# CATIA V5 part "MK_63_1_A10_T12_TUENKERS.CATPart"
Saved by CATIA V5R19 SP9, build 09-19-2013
Part number: MK_63_1_A10_T12_TUENKERS
Material "MISCHDICHTE": density 5230.5 kg/m3, Young's modulus 2e+11 Pa, Poisson ratio 0.266
Bounding box of the stored display mesh (mm): x -193.5 to 132.266, y -121.5 to 144, z -40 to 122.161
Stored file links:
  G:\Konstruktion\Modelle\Catia_V5\MK_63_1_A10_T12_TUENKERS.CATPart
  G:\Konstruktion\Modelle\Catia_V5\Spannarme\SPANNARM_KPL_63_A10_217498_TUENKERS.CATPart
  C:\Catia\Tuenkers_B19SP9HF86_64\win_b64\reffiles\standard\MetricThickPitch.txt
  G:\Konstruktion\Modelle\Catia_V5\MK_63_1_A10_T00_TUENKERS.CATPart
  G:\Konstruktion\Modelle\Catia_V5\MK2_63_1_A40_T12_TUENKERS.CATPart
  HANDHEBEL_KPL_50_63_TUENKERS.CATPart
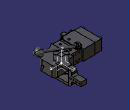
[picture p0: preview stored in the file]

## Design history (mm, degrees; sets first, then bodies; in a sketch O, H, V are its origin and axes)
AxisSystem1: origin (0, 0, 0), X (1, 0, 0), Y (0, 1, 0), Z (0, 0, 1)
Body1 (main body)
  Body2 "*DIT1\\*DIT2\\"
    Solid1: solid without history
  Assemble1: tool Body2
  Body3 "*DIT1\\*DIT3"
    Solid2 "Solid.1": solid without history
  Assemble2: tool Body3
  Body4 "*DIT1\\*DIT12\\*DIT16\\"
    Solid3 "Solid.1": solid without history
  Assemble3: tool Body4
  Body5 "*DIT1\\*DIT12\\*DIT17\\"
    Solid4 "Solid.1": solid without history
  Assemble4: tool Body5
  Body6 "*DIT1\\*DIT12\\MK_MK2_63_1_A10_A11_A12_T12_081112_3D_xSET4_2.1"
    Solid5 "Solid.1": solid without history
    Body7 "*DIT1\\*DIT12\\MK_MK2_63_1_A10_A11_A12_T12_081112_3D_xSET4_2.1\\Body.11 ( *SOL16 - wsp GEHAEUSE -  )"
      Solid6 "Solid.1": solid without history
    Add1 "*DIT1\\*DIT12\\MK_MK2_63_1_A10_A11_A12_T12_081112_3D_xSET4_2.1\\Body.11 ( *SOL16 - wsp GEHAEUSE -  )": tool Body7
    Body8 "*DIT1\\*DIT12\\MK_MK2_63_1_A10_A11_A12_T12_081112_3D_xSET4_2.1\\Body.12 ( *SOL17 - wsp GEHAEUSE -  )"
      Solid7 "Solid.1": solid without history
    Add2 "*DIT1\\*DIT12\\MK_MK2_63_1_A10_A11_A12_T12_081112_3D_xSET4_2.1\\Body.12 ( *SOL17 - wsp GEHAEUSE -  )": tool Body8
    Body9 "*DIT1\\*DIT12\\MK_MK2_63_1_A10_A11_A12_T12_081112_3D_xSET4_2.1\\Body.14 ( *SOL18 - wsp GEHAEUSE -  )"
      Solid8 "Solid.1": solid without history
    Add3 "*DIT1\\*DIT12\\MK_MK2_63_1_A10_A11_A12_T12_081112_3D_xSET4_2.1\\Body.14 ( *SOL18 - wsp GEHAEUSE -  )": tool Body9
  Assemble5: tool Body6
  Body10 "*DIT1\\MK_MK2_63_1_A10_A11_A12_T12_081112_3D_xSET2_1.1"
    Solid9 "Solid.1": solid without history
  Assemble6: tool Body10
  Rotate1: Axis edge [XY plane of AxisSystem1 | ZX plane of AxisSystem1], Angle 90, ToTransfor Assemble6
  Body11
    Body12 "*DIT1\\MK_MK2_63_1_A10_A11_A12_T12_081112_3D_xSET2_1.1\\Body.2 ( *SOL2 - wsp MK_MK2 63_1 -  )"
      Solid10 "Solid.1": solid without history
    Assemble7: tool Body12
    Body13 "*DIT1\\MK_MK2_63_1_A10_A11_A12_T12_081112_3D_xSET2_1.1\\Body.3 ( *SOL3 - wsp MK_MK2 63_1 -  )"
      Solid11 "Solid.1": solid without history
    Assemble8: tool Body13
    Body14 "*DIT1\\MK_MK2_63_1_A10_A11_A12_T12_081112_3D_xSET2_1.1\\Body.4 ( *SOL4 - wsp MK_MK2 63_1 -  )"
      Solid12 "Solid.1": solid without history
    Assemble9: tool Body14
    Body15 "*DIT1\\MK_MK2_63_1_A10_A11_A12_T12_081112_3D_xSET2_1.1\\Body.5 ( *SOL5 - wsp MK_MK2 63_1 -  )"
      Solid13 "Solid.1": solid without history
    Assemble10: tool Body15
    Body16 "*DIT1\\MK_MK2_63_1_A10_A11_A12_T12_081112_3D_xSET2_1.1\\Body.6 ( *SOL6 - wsp MK_MK2 63_1 -  )"
      Solid14 "Solid.1": solid without history
    Assemble11: tool Body16
    Rotate2: Axis edge, Angle 90, ToTransfor Assemble11
    Translate1: Direction edge [YZ plane of AxisSystem1 | XY plane of AxisSystem1], Length -1, ToTransfor Rotate2
  Assemble12: tool Body11
Body17 "Spannarm_kpl_63_A10_217498_Tuenkers", material "Steel"
  Sketch1 on xy-plane, origin (0, 0, 0), H (1, 0, 0), V (0, 1, 0)
    line L1 (43, 144) -> (15, 144)
    arc A1 centre (21.5, 11.6005) radius 20 from (35.6421, -2.5416) to (41.5, 11.6005) ccw
    line L2 (35.6421, -2.5416) -> (19.0919, -19.0919)
    line L3 (10.9602, 10.9602) -> (10.9602, -10.9602)
    line L4 (10.9602, 10.9602) -> (-10.9602, 10.9602)
    line L5 (-19.0919, 19.0919) -> (-10.9602, 10.9602)
    line L6 (10.6421, 48.8259) -> (-19.0919, 19.0919)
    line L7 (16.5, 62.968) -> (16.5, 78.0635)
    line L8 (43, 144) -> (43, 80)
    line L9 (10.9602, -10.9602) -> (19.0919, -19.0919)
    point P7 (10.9602, 10.9602)
    point P10 (-1.4396, 36.7442)
    point P11 (73, 37.6447)
    point P12 (45, 51.7188)
    reference intersected line E1 through (0, 0) direction (-0.7071, 0.7071)
    reference intersected line E2 through (0, 0) direction (-0.7071, 0.7071)
    reference intersected line E3 through (0, 0) direction (-0.7071, 0.7071)
    reference intersected line E4 through (0, 0) direction (0, 1) from yz-plane
    reference intersected line E5 through (0, 0) direction (-1, 0) from zx-plane
    line L10 (41.5, 78.0635) -> (41.5, 11.6005)
    line L11 (15, 80) -> (15, 144)
    arc A2 centre (-3.5, 62.968) radius 20 from (10.6421, 48.8259) to (16.5, 62.968) ccw
    arc A3 centre (14.5, 78.0635) radius 2 from (16.5, 78.0635) to (15, 80) ccw
    arc A4 centre (43.5, 78.0635) radius 2 from (41.5, 78.0635) to (43, 80) cw
    reference intersected line E6 through (0, 0) direction (0, 1) from yz-plane
    radius A1 = 20
    angle L4 L5 = 45
    distance P7 L2 = 27
    distance L2 L6 = 54
    angle L2 L9 = 90
    distance P7 E1 = 15.5
    distance E4 L3 = 10.9602
    distance E5 L1 = 144
    distance P10 L1 = 107.2558
    radius A4 = 2
    radius A3 = 2
    distance L10 L8 = 1.5
    distance L7 L10 = 25
    distance E6 L11 = 15
    distance L11 L7 = 1.5
    length L8 = 64
    radius A2 = 20
    length L11 = 64
    tangency: A1 L2, A1 L10, A4 L10, A2 L7, L6 A2, A3 L7
    coincidence: L9 E2, L5 E3, L6 P10
  Pad1: profile Sketch1, direction (0, 0, 1), length 39, opposite side length 39
  Chamfer1: length 0.1, angle 45, on edge [face of Pad1 from Sketch1.L3 | end face of Pad1]; edge [face of Pad1 from Sketch1.L4 | end face of Pad1]; edge [start face of Pad1 | face of Pad1 from Sketch1.L4]; edge [start face of Pad1 | face of Pad1 from Sketch1.L3]
  Sketch2 on face of Pad1 from Sketch1.L8, origin (43, 0, 0), H (0, 1, 0), V (0, 0, 1)
    line L1 (144, -10) -> (144, 10)
    line L2 (103, 10) -> (144, 10)
    arc A1 centre (103, 18) radius 8 from (103, 10) to (95, 18) cw
    line L3 (95, 24.9808) -> (95, 18)
    line L4 (-20, 39) -> (70, 39)
    line L5 (-20, 39) -> (-20, 28)
    line L6 (74, 28) -> (-20, 28)
    arc A2 centre (74, 22) radius 6 from (74, 28) to (80, 22) cw
    line L7 (80, 22) -> (80, -22)
    arc A3 centre (74, -22) radius 6 from (80, -22) to (74, -28) cw
    line L8 (-20, -28) -> (74, -28)
    line L9 (-20, -28) -> (-20, -39)
    line L10 (-20, -39) -> (70, -39)
    line L11 (95, -24.9808) -> (95, -18)
    arc A4 centre (103, -18) radius 8 from (95, -18) to (103, -10) cw
    line L12 (103, -10) -> (144, -10)
    reference intersected line E1 through (0, 0) direction (-1, 0) from xy-plane
    reference intersected line E2 through (0, 0) direction (0, 1) from zx-plane
    reference intersected line E3 through (0, 0) direction (0, 1) from zx-plane
    reference intersected line E4 through (0, 0) direction (0, 1) from zx-plane
    line L13 (-30, -44) -> (160, -44)
    line L14 (160, -44) -> (160, 44)
    line L15 (160, 44) -> (-30, 44)
    line L16 (-30, 44) -> (-30, -44)
    reference intersected line E5 through (0, 0) direction (-1, 0) from xy-plane
    reference intersected line E6 through (0, 0) direction (0, 1) from zx-plane
    line L17 (72.5882, -38.6593) -> (87.5882, -34.64)
    line L18 (87.5882, 34.64) -> (72.5882, 38.6593)
    arc A5 centre (85, 24.9808) radius 10 from (95, 24.9808) to (87.5882, 34.64) ccw
    arc A6 centre (70, 29) radius 10 from (72.5882, 38.6593) to (70, 39) ccw
    point P23 (70, 39)
    arc A7 centre (70, -29) radius 10 from (72.5882, -38.6593) to (70, -39) cw
    point P26 (70, -39)
    arc A8 centre (85, -24.9808) radius 10 from (95, -24.9808) to (87.5882, -34.64) cw
    distance L12 E1 = 10
    distance L12 L2 = 20
    distance L4 L10 = 78
    distance L6 L8 = 56
    distance L10 L12 = 29
    distance L8 L10 = 11
    radius A2 = 6
    radius A3 = 6
    radius A1 = 8
    radius A4 = 8
    distance L7 E2 = 80
    distance L3 E3 = 95
    distance L1 L5 = 164
    distance E4 L1 = 144
    distance L16 L14 = 190
    distance L15 L13 = 88
    distance L13 E5 = 44
    distance L14 E6 = 160
    angle L18 L4 = 15
    distance P23 L3 = 25
    radius A6 = 10
    radius A5 = 10
    angle L10 L17 = 15
    distance L11 P26 = 25
    radius A7 = 10
    radius A8 = 10
    tangency: L6 A2, A2 L7, L7 A3, A3 L8, L3 A1, A1 L2, A4 L12, A4 L11, A5 L3, A5 L18, A6 L18, A6 L4, A7 L17, A7 L10, A8 L11, A8 L17
    vertical: L1 V, L14 V, L16 V
    horizontal: L12 H, L13 H, L15 H
    coincidence: L5 L9, L11 L3
  Pocket1: profile Sketch2, direction (-1, 0, 0), length 95
  Sketch3 on face of Pad1 from Sketch1.L8, origin (43, 131.0889, -0.3784), H (0, 1, 0), V (0, 0, 1)
    point P1 (3.9111, 0.3784)
    reference intersected line E1 through (0, 0.3784) direction (-1, 0) from xy-plane
    reference intersected line E2 through (-131.0889, 0) direction (0, 1) from zx-plane
    reference intersected line E3 through (-131.0889, 0) direction (0, 1) from zx-plane
    reference intersected line E4 (12.9111, -38.6216) -> (-51.0889, -38.6216) from start face of Pad1
    distance P1 E2 = 135
    distance E3 E4 = 0
    coincidence: P1 E1
  Hole1: placed by Sketch3, at (43, 135, 0) direction (-1, 0, 0), diameter 6, through (limit type 6)
  Sketch4 on face of Pad1 from Sketch1.L8, origin (43, 113.9529, 0.5693), H (0, 1, 0), V (0, 0, 1)
    point P1 (-8.9529, -0.5693)
    reference projected point E1 (21.0471, -0.5693) from axis of face of Hole1
    reference intersected line E2 through (0, -0.5693) direction (-1, 0) from xy-plane
    distance P1 E1 = 30
    coincidence: P1 E2
  Hole2: placed by Sketch4, at (43, 105, 0) direction (-1, 0, 0), diameter 6, through (limit type 6)
  Sketch5 on face of Pad1 from Sketch1.L8, origin (43, 123.4122, -0.1089), H (0, 1, 0), V (0, 0, 1)
    point P1 (-3.4122, 0.1089)
    reference projected point E1 (11.5878, 0.1089) from axis of face of Hole1
    reference projected point E2 (-18.4122, 0.1089) from axis of face of Hole2
    distance P1 E1 = 15
    distance E2 P1 = 15
  Hole3: placed by Sketch5, at (43, 120, 0) direction (-1, 0, 0), diameter 9, through (limit type 6)
  Sketch6 on face of Pad1 from Sketch1.L8, origin (43, 93.5248, 1.4062), H (0, 1, 0), V (0, 0, 1)
    point P1 (-3.5248, -1.4062)
    reference projected point E1 (26.4752, -1.4062) from axis of face of Hole3
    reference projected point E2 (11.4752, -1.4062) from axis of face of Hole2
    distance P1 E1 = 30
    distance P1 E2 = 15
  Hole4: placed by Sketch6, at (43, 90, 0) direction (-1, 0, 0), diameter 9, through (limit type 6)
  Sketch7 on face of Pad1 from Sketch1.L9, origin (13.7879, -13.7879, 28.7565), H (0.7071, -0.7071, 0), V (0, 0, 1)
    point P1 (0.5009, 4.2435)
    reference intersected line E1 through (0, -28.7565) direction (-1, 0) from xy-plane
    reference projected line E2 (-19.4991, -67.7565) -> (-19.4991, 10.2435) from edge [face of Pad1 from Sketch1.L3 | face of Pad1 from Sketch1.L4]
    distance P1 E1 = 33
    distance E2 P1 = 20
  Hole5: placed by Sketch7, at (14.1421, -14.1421, 33) direction (0.7071, 0.7071, 0), diameter 6.647, depth 18, V-bottom angle 120, threaded "M8", thread diameter 8, thread depth 15, pitch 1.25
  RectPattern1: of Hole5, direction 1 instances 2, spacing 66, along edge [face of Pad1 from Sketch1.L3 | face of Pad1 from Sketch1.L4] reversed, direction 2 instances 2, spacing 40, along edge [face of Pad1 from Sketch1.L9 | face of Pocket1] reversed
  Sketch8 on face of Pocket1 from Sketch2.L6, origin (0, 0, 28), H (1, 0, 0), V (0, -1, 0)
    line L1 (19.0919, 19.0919) -> (35.6421, 2.5416)
    line L2 (36.7245, 1.3692) -> (-1.4142, -36.7696)
    line L3 (-1.4142, -36.7696) -> (-19.0919, -19.0919)
    line L4 (-19.0919, -19.0919) -> (-10.96, -10.96)
    line L5 (-10.96, -10.96) -> (10.96, -10.96)
    point P5 (10.96, -10.96)
    line L6 (10.96, -10.96) -> (10.96, 10.96)
    line L7 (10.96, 10.96) -> (19.0919, 19.0919)
    reference intersected line E1 through (0, 0) direction (0.7071, -0.7071)
    reference intersected line E2 through (0, 0) direction (0.7071, 0.7071)
    reference intersected line E3 through (0, 0) direction (0.7071, -0.7071)
    arc A1 centre (21.5, -11.6005) radius 20 from (35.6421, 2.5416) to (36.7245, 1.3692) cw
    reference intersected line E4 through (0, 0) direction (0, 1) from yz-plane
    distance E1 L1 = 27
    distance L3 L1 = 54
    distance L7 L2 = 25
    angle L6 L5 = 90
    radius A1 = 20
    length L2 = 53.9363
    distance E4 L6 = 10.96
    coincidence: E2 L7, L4 L7, P5 E3
    tangency: A1 L1
  Pad2: profile Sketch8, direction (0, 0, -1), length 1
  Mirror1: of Pad2, Sketch8, about xy-plane
  Body18 "KLEMMFLANSCH KPL"
    Sketch9 on xy-plane, origin (0, 0, 0), H (1, 0, 0), V (0, 1, 0)
      line L1 (-20.5061, 17.6777) -> (-31.1375, 7.0463)
      line L2 (-31.1375, 7.0463) -> (-19.1167, -4.9745)
      line L3 (-19.1167, -4.9745) -> (-25.4806, -11.3385)
      line L4 (-25.4806, -11.3385) -> (-11.3385, -25.4806)
      line L5 (-11.3385, -25.4806) -> (-4.9745, -19.1167)
      line L6 (-4.9745, -19.1167) -> (7.0463, -31.1375)
      line L7 (7.0463, -31.1375) -> (19.0671, -19.1167)
      line L8 (19.0671, -19.1167) -> (10.9106, -10.9602)
      line L9 (10.9106, -10.9602) -> (-10.9602, -10.9602)
      point P10 (-10.9602, -10.9602)
      line L10 (-10.9602, -10.9602) -> (-10.9602, 8.1317)
      line L11 (-10.9602, 8.1317) -> (-20.5061, 17.6777)
      reference intersected line E1 through (0, 0) direction (-0.7071, 0.7071)
      reference intersected line E2 through (0, 0) direction (-0.7071, 0.7071)
      reference intersected line E3 through (0, 0) direction (-0.7071, -0.7071)
      distance L4 L8 = 26
      distance L7 L5 = 17
      distance L5 L3 = 20
      distance L7 L1 = 54
      distance L4 L6 = 9
      distance E1 P10 = 15.5
      distance L11 E2 = 2
      distance L11 L8 = 1.965
      angle L11 L10 = 135
      angle L9 L8 = 45
      distance L7 P10 = 27
      distance E3 L7 = 27
      coincidence: L2 L6
    Pad3: profile Sketch9, direction (0, 0, 1), length 39, opposite side length -27
    Chamfer2: length 0.1, angle 45, on edge [face of Pad3 from Sketch9.L9 | end face of Pad3]; edge [face of Pad3 from Sketch9.L10 | end face of Pad3]
    Sketch10 on face of Pad3 from Sketch9.L6, origin (-12.0456, -12.0456, 0), H (0.7071, -0.7071, 0), V (0, 0, 1)
      circle A1 centre (20, 33) radius 4
      point P1 (20, 33)
      circle A2 centre (-20, 33) radius 4
      point P2 (-20, 33)
      reference projected line E1 (-27, 27) -> (-10, 27) from edge [start face of Pad3 | face of Pad3 from Sketch9.L2]
      reference projected line E2 (10, 27) -> (27, 27) from edge [start face of Pad3 | face of Pad3 from Sketch9.L6]
      reference projected line E3 (27, 27) -> (27, 39) from edge [face of Pad3 from Sketch9.L7 | face of Pad3 from Sketch9.L6]
      reference projected line E4 (-27, 27) -> (-27, 39) from edge [face of Pad3 from Sketch9.L2 | face of Pad3 from Sketch9.L1]
      radius A1 = 4
      radius A2 = 4
      distance E1 P2 = 6
      distance P1 E2 = 6
      distance E3 P1 = 7
      distance P2 E4 = 7
    Pad4: profile Sketch10, direction (0.7071, 0.7071, 0), length 20
    Sketch11 on face of Pad4, origin (-12.0456, -12.0456, 0), H (0.7071, -0.7071, 0), V (0, 0, 1)
      circle A1 centre (20, 33) radius 6.5
      point P1 (20, 33)
      circle A2 centre (-20, 33) radius 6.5
      point P2 (-20, 33)
      reference projected line E1 (-27, 27) -> (-27, 39) from edge [face of Pad3 from Sketch9.L2 | face of Pad3 from Sketch9.L1]
      reference projected line E2 (27, 27) -> (27, 39) from edge [face of Pad3 from Sketch9.L7 | face of Pad3 from Sketch9.L6]
      reference projected line E3 (-27, 27) -> (-10, 27) from edge [start face of Pad3 | face of Pad3 from Sketch9.L2]
      reference projected line E4 (10, 27) -> (27, 27) from edge [start face of Pad3 | face of Pad3 from Sketch9.L6]
      radius A1 = 6.5
      radius A2 = 6.5
      distance E1 P2 = 7
      distance E2 P1 = 7
      distance E3 P2 = 6
      distance E4 P1 = 6
    Pad5: profile Sketch11, direction (-0.7071, -0.7071, 0), length 1.4
    Chamfer3: length 0.1, angle 45, on edge [face of Pad5 from Sketch11.A1 | end face of Pad5]; edge [face of Pad5 from Sketch11.A2 | end face of Pad5]
    Sketch12 on end face of Pad5, origin (-13.0355, -13.0355, 0), H (0.7071, -0.7071, 0), V (0, 0, 1)
      circle A1 centre (20, 33) radius 6.5
      point P1 (20, 33)
      circle A2 centre (-20, 33) radius 6.5
      point P2 (-20, 33)
      reference projected line E1 (10, 27) -> (27, 27) from edge [start face of Pad3 | face of Pad4]
      reference projected line E2 (27, 27) -> (27, 39) from edge [face of Pad3 from Sketch9.L7 | face of Pad3 from Sketch9.L6]
      reference projected line E3 (-27, 27) -> (-27, 39) from edge [face of Pad3 from Sketch9.L2 | face of Pad3 from Sketch9.L1]
      reference projected line E4 (-27, 27) -> (-10, 27) from edge [start face of Pad3 | face of Pad4]
      radius A1 = 6.5
      radius A2 = 6.5
      distance E1 P1 = 6
      distance E2 P1 = 7
      distance E3 P2 = 7
      distance E4 P2 = 6
    Pad6: profile Sketch12, direction (-0.7071, -0.7071, 0), length 8
    Fillet1: radius 0.5, on end face of Pad6; edge [face of Pad6 from Sketch12.A1 | end face of Pad6]
    Mirror2: of the body so far, about xy-plane
  Assemble13: tool Body18
Body19 "Handhebel_KPL_218625_TUENKERS.1"
  Solid15: solid without history
  Body20 "Handhebel_KPL_218625_TUENKERS.2"
    Solid16: solid without history
  Assemble14: tool Body20
  Translate2: Direction edge [XY plane of AxisSystem1 | ZX plane of AxisSystem1], ToTransfor Assemble14, Length -86
  Translate3: Direction edge [ZX plane of AxisSystem1 | YZ plane of AxisSystem1], ToTransfor Translate2, Length 28
  Translate4: Direction edge [YZ plane of AxisSystem1 | XY plane of AxisSystem1], ToTransfor Translate3, Length -4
